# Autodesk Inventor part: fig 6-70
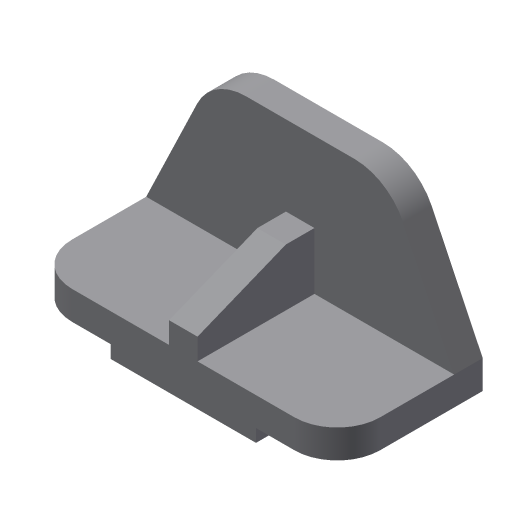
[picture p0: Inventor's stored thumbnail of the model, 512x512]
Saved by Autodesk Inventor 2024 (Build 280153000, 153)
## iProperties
Shininess: 77.0
Length Units: 11269
Angle Units: 11279
Time Units: 11290
Mass Units: 11283
Length Display Precision: 3
Angle Display Precision: 2
Created: 2001-12
Part Number: fig 6-70
Document SubType Name: Modeling
Designer: Renu Muthoo
Density: 1 g/cm^3
Material: Generic
Appearance: Default
Density: 0.0
Volumn: 0.0
Area: 0.0
PropertySet Name: Model Information
Control State: 0
Master: False
Checked Out: False
Author: Renu Muthoo
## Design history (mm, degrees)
sketch "Sketch2"
  geometry: L1 (-67.219, 19.116)-(148.781, 19.116); L2 (148.781, 19.116)-(148.781, -0.884); L3 (-67.219, -0.884)-(-67.219, 19.116); L4 (-10.219, -0.884)-(-10.219, -9.884); L5 (-10.219, -9.884)-(91.781, -9.884); L6 (91.781, -9.884)-(91.781, -0.884); L7 (148.781, -0.884)-(91.781, -0.884); L8 (-10.219, -0.884)-(-67.219, -0.884)
  constraints: 16 end point, 5 parallel, 4 perpendicular, 2 equal length, 1 horizontal
  dimensions: "d0" = 102 distance of L4.end L5.end; "d1" = 57 distance of L4.start L3.start; "d2" = 29 distance between parallel lines of L1 L5; "d3" = 20 distance of L1.end L2.end
extrude "Extrusion1" new body sketch "Sketch2" distance "d4" = 102; taper "d5" = 0 deg
sketch "Sketch3"
  geometry: L1 (67.219, -19.116)-(-148.781, -19.116) reference; L2 (67.219, -19.116)-(31.475, -93.564); L3 (-2.781, -115.116)-(-78.781, -115.116); L4 (-113.038, -93.564)-(-148.781, -19.116); A1 r 38 centre (-2.781, -77.116) between (-2.781, -115.116) and (31.475, -93.564); A2 r 38 centre (-78.781, -77.116) between (-113.038, -93.564) and (-78.781, -115.116)
  constraints: 6 end point, 4 point on circle, 4 tangent, 2 centre point, 1 equal length, 1 equal radius, 1 parallel
  dimensions: "d6" = 96 distance between parallel lines of L3 L1; "d7" = 38 radius of A1; "d8" = 76 distance of A2.centre A1.centre
extrude "Extrusion2" join sketch "Sketch3" distance "d9" = 20; taper "d10" = 0 deg
fillet "Fillet1" dims "d11" = 30
workplane "Work Plane1"
sketch "Sketch7"
  geometry: L1 (0, -82)-(-15, -82); L2 (-15, -82)-(-40, -20); L3 (-40, -20)-(-40, 0); L4 (0, -82)-(20, -82) reference; L5 (0, 0)-(-74.447, 0) reference
  constraints: 6 end point, 2 point on line, 1 horizontal, 1 perpendicular
  dimensions: "d32" = 20 distance of L2.end L3.end; "d33" = 15 distance of L1.start L1.end; "d34" = 40 distance of L5.start L3.end
feature "Rib4" sketch "Sketch7" dims "d55" = 1, "d56" = 20, "d57" = 0
body "Solid1"
other parameters: "d12" = -108
